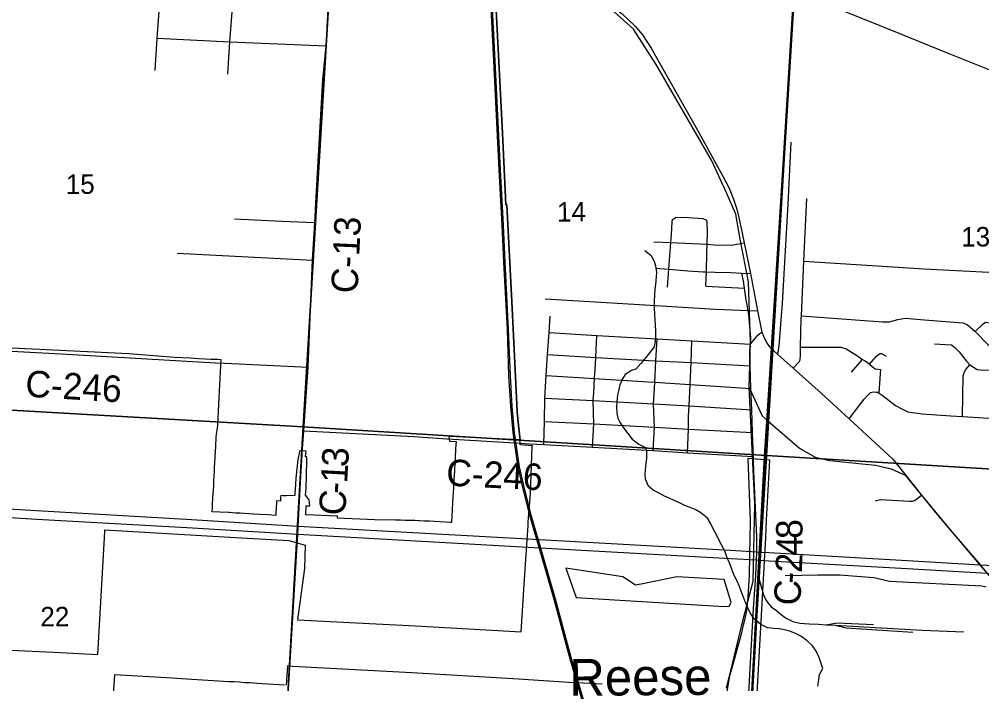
# Model space of a CAD drawing. Extents: x 114604 to 551442, y 316898 to 567001.
# Drawn here: x 211594 to 222509, y 352635 to 360166 of the extents above; entities that cross this region are included whole.
import ezdxf

# ---------------------------------------------------------------- set-up
doc = ezdxf.new("R2010")
doc.units = 0
for name, color, linetype in [('_CIVIL_CONSTRUCTION', 7, 'Continuous'), ('GE_P_Alignment_1000_Bearings', 7, 'Continuous'), ('GE_P_Alignment_1000_Cardinal_Points', 7, 'Continuous'), ('GE_P_Alignment_100_Cardinal_Points', 7, 'Continuous'), ('GE_P_Alignment_100_Stations', 7, 'Continuous'), ('GE_P_Alignment_500_Bearings', 7, 'Continuous'), ('GE_P_Alignment_500_Stations', 7, 'Continuous'), ('MT_X_Edge_Line', 7, 'Continuous'), ('PM_P_Cells', 7, 'Continuous'), ('PM_P_CL_Double_Solid', 7, 'Continuous'), ('PV_X_Curb', 7, 'Continuous'), ('SN_P_Signs', 7, 'Continuous')]:
    doc.layers.add(name, color=color, linetype=linetype)

msp = doc.modelspace()

# ---------------------------------------------------------------- linework, layer by layer
at = {"layer": 'GE_P_Alignment_1000_Bearings'}
msp.add_line((220743, 353304), (220845, 353298), dxfattribs=at)
for points in [[(218631, 350263), (217854, 352934), (217675, 353594), (217531, 354094), (217400, 354544), (217315, 354882), (217268, 355093), (217250, 355195), (217209, 355484), (217183, 355777), (217163, 356127), (217144, 356648), (217105, 357415), (217084, 357831), (217052, 358461), (216986, 359770), (216941, 360658), (216921, 360934), (216917, 360995), (216880, 361603), (216781, 362352), (216730, 362595), (216600, 362827)], [(216600, 362827), (216766, 362658), (216806, 362616), (216908, 362516), (216997, 362427), (217193, 362237), (217353, 362078), (217600, 361872), (217668, 361817), (217820, 361700), (217968, 361593), (218214, 361432), (218573, 361229), (218809, 361119), (219483, 360846), (219708, 360755), (220389, 360483), (221214, 360151), (221568, 360008), (222154, 359772), (222855, 359492)], [(219870, 355993), (219885, 356503), (219863, 357189), (219771, 357673), (219721, 357957), (219619, 358192), (219445, 358570), (218816, 359653), (218559, 360054), (218303, 360283), (218036, 360470), (217786, 360675), (217423, 361033), (217160, 361368), (217005, 361592), (216861, 361910), (216806, 362147), (216780, 362442), (216805, 362619)], [(218617, 350258), (217839, 352930), (217660, 353590), (217517, 354089), (217385, 354540), (217300, 354878), (217253, 355090), (217235, 355193), (217194, 355482), (217168, 355776), (217147, 356126), (217129, 356648), (217090, 357414), (217069, 357830), (217037, 358460), (216971, 359769), (216926, 360657), (216908, 360908), (216852, 361462)], [(219874, 352054), (219970, 353816), (220046, 355214), (220072, 355612), (220250, 358400), (220377, 360484)], [(219886, 352054), (219983, 353815), (220059, 355213), (220084, 355612), (220262, 358399), (220389, 360483)], [(219615, 352586), (219675, 352830), (219804, 353363), (219917, 353797), (219937, 354674), (219870, 355993)], [(219870, 355993), (220018, 355673), (220083, 355614)], [(220083, 355614), (220442, 355306), (220619, 355201), (220787, 355164), (221154, 355126), (221307, 355112), (221481, 355069), (221639, 354999), (222004, 354554), (222478, 353990), (222796, 353621), (223021, 353436), (223451, 353137), (223888, 352925), (224349, 352693), (224986, 352370)], [(219983, 353815), (220011, 353723), (220030, 353653), (220052, 353597), (220083, 353552), (220122, 353507), (220180, 353464), (220237, 353416), (220290, 353379), (220366, 353342), (220446, 353320), (220550, 353315), (220658, 353309), (220743, 353304)], [(220743, 353304), (220866, 353326), (221281, 353305)], [(220845, 353298), (220971, 353268), (221729, 353218)], [(220845, 353298), (221106, 353282), (221833, 353242), (222305, 353224)]]:
    msp.add_lwpolyline(points, dxfattribs=at)
at = {"layer": 'GE_P_Alignment_1000_Cardinal_Points'}
msp.add_line((213386, 357516), (214921, 357436), dxfattribs=at)
for points in [[(213137, 359584), (213159, 359950), (213235, 360975)], [(213958, 359543), (213982, 359911), (214061, 360928)], [(213159, 359950), (213982, 359911), (215075, 359866)], [(214037, 357903), (214571, 357878), (214946, 357861)]]:
    msp.add_lwpolyline(points, dxfattribs=at)
at = {"layer": 'GE_P_Alignment_100_Cardinal_Points'}
for p, q in [((219381, 357139), (219817, 357117)), ((221030, 356166), (221158, 356311))]:
    msp.add_line(p, q, dxfattribs=at)
for points in [[(220195, 356368), (220211, 356464), (220250, 356948), (220312, 358071), (220347, 358771)], [(220371, 356211), (220437, 356285), (220448, 356307), (220452, 356359), (220455, 356451), (220462, 356783), (220463, 356804), (220492, 357425), (220524, 358133)], [(218946, 357130), (218961, 357333), (218983, 357635), (218990, 357728), (218997, 357869), (219002, 357897), (219018, 357905)], [(219018, 357905), (219040, 357923), (219182, 357919), (219347, 357908), (219389, 357889)], [(219381, 357139), (219386, 357302), (219393, 357520), (219395, 357615), (219398, 357749), (219395, 357869), (219389, 357889)], [(218791, 357644), (218983, 357635), (219395, 357615), (219474, 357611), (219612, 357604), (219690, 357609), (219816, 357633)], [(218808, 357345), (218961, 357333), (219177, 357315), (219349, 357303), (219386, 357302), (219487, 357298), (219662, 357294), (219789, 357288), (219885, 357284)], [(220492, 357425), (221855, 357339), (222660, 357294), (223022, 357273)], [(219888, 356482), (219889, 356559), (219879, 356683), (219868, 356815), (219859, 356865), (219839, 356985), (219817, 357117), (219806, 357196), (219789, 357288)], [(217557, 356997), (218564, 356938), (219488, 356881), (219859, 356865), (219967, 356860)], [(217543, 355346), (217552, 355607), (217555, 355873), (217571, 356129), (217586, 356366), (217602, 356615), (217614, 356799)], [(220463, 356804), (221382, 356735), (221461, 356738), (221558, 356763), (221642, 356778), (221861, 356760), (222296, 356727), (222344, 356705), (222435, 356628), (222579, 356481), (222606, 356459), (222629, 356455), (222967, 356429)], [(222435, 356628), (222525, 356713), (222550, 356731), (222576, 356730), (222595, 356724), (222697, 356699)], [(217602, 356615), (218145, 356582), (218827, 356544), (219223, 356523), (219888, 356482)], [(218093, 355316), (218110, 355580), (218104, 355844), (218110, 355933), (218119, 356093), (218128, 356256), (218132, 356332), (218145, 356582)], [(219888, 356482), (219914, 356516), (219937, 356545), (219951, 356564), (219970, 356586), (219994, 356603), (220016, 356618)], [(218782, 355278), (218797, 355543), (218787, 355809), (218793, 355922), (218800, 356054), (218813, 356295), (218827, 356544)], [(219171, 355252), (219185, 355522), (219184, 355667), (219190, 355786), (219202, 356026), (219213, 356277), (219223, 356523)], [(219921, 355210), (219909, 355481), (219902, 355739), (219891, 355982), (219882, 356237), (219877, 356400), (219881, 356457), (219888, 356482)], [(221972, 356489), (222166, 356475), (222203, 356447), (222253, 356397), (222337, 356290), (222372, 356251), (222375, 356248), (222416, 356223), (222456, 356197), (222490, 356193), (222626, 356187)], [(217586, 356366), (218132, 356332), (218805, 356295), (218813, 356295), (219213, 356277), (219882, 356237)], [(220455, 356451), (220911, 356449), (220971, 356432), (221098, 356353), (221158, 356311), (221189, 356290), (221227, 356264), (221235, 356257), (221266, 356229), (221300, 356205), (221366, 356196)], [(221235, 356257), (221314, 356347), (221352, 356378), (221372, 356376), (221425, 356349)], [(222289, 355664), (222298, 356125), (222308, 356163), (222328, 356198), (222372, 356251)], [(221344, 355929), (221357, 356093), (221366, 356196)], [(217571, 356129), (218119, 356093), (218795, 356054), (218800, 356054), (219198, 356026), (219202, 356026), (219891, 355982)], [(221007, 355637), (221177, 355862), (221213, 355903), (221247, 355937), (221283, 355944), (221313, 355940), (221329, 355939), (221344, 355929)], [(221344, 355929), (221381, 355905), (221462, 355840), (221531, 355790), (221601, 355749), (221670, 355716), (221834, 355693), (222157, 355673), (222289, 355664), (222590, 355643), (222596, 355642), (222674, 355626), (222741, 355598), (222785, 355569), (222819, 355545), (222872, 355536), (222909, 355533), (223397, 355499)], [(217555, 355873), (218104, 355844), (218787, 355809), (219190, 355786), (219902, 355739)], [(217552, 355607), (218110, 355580), (218797, 355543), (219185, 355522), (219909, 355481)], [(221304, 354709), (221359, 354722), (221691, 354705), (221725, 354705), (221753, 354715), (221825, 354774)], [(220281, 353860), (220651, 353871), (220769, 353870), (220898, 353868), (221286, 353838), (221463, 353797), (222511, 353744), (222560, 353735)]]:
    msp.add_lwpolyline(points, dxfattribs=at)
at = {"layer": 'GE_P_Alignment_100_Stations'}
for points in [[(211491, 353017), (211986, 352991), (212486, 352965), (212565, 354355), (212566, 354381), (213982, 354298), (214650, 354258), (214838, 354207), (214828, 353940), (214803, 353749), (214751, 353359), (216087, 353293), (216490, 353270), (217285, 353225), (217318, 353759), (217338, 354042), (217364, 354429), (217366, 354468), (217390, 354795), (217412, 355319), (217413, 355333), (217274, 355342), (217275, 355376), (217275, 355399), (217254, 355560), (217242, 355718), (217232, 355879), (217179, 356967), (217125, 358062), (217112, 358063), (217073, 358876), (217044, 359466), (216980, 360710)], [(216980, 360710), (217044, 359466), (217073, 358876), (217112, 358063), (217125, 358062), (217179, 356967), (217232, 355879), (217242, 355718), (217254, 355560), (217275, 355399), (216466, 355438), (216472, 355384), (216548, 355382), (216543, 355298), (216537, 355197), (216535, 355148), (216529, 355049), (216526, 355000), (216523, 354950), (216520, 354900), (216517, 354850), (216514, 354800), (216511, 354749), (216508, 354699), (216502, 354594), (216499, 354540), (216495, 354461), (216482, 354462), (216425, 354465), (216298, 354473), (216245, 354476), (216189, 354479), (216134, 354482), (216122, 354483), (216080, 354484), (216025, 354485), (215971, 354486), (215916, 354487), (215861, 354487), (215624, 354491), (215203, 354510), (215204, 354536), (214845, 354551), (214848, 354652), (214889, 354651), (214881, 354720), (214841, 354773), (214846, 354849), (214848, 354900), (214852, 354955), (214854, 355208), (214842, 355208), (214847, 355270), (214775, 355278), (214756, 355197), (214750, 355147), (214745, 355098), (214740, 355048), (214733, 354982), (214732, 354974), (214727, 354892), (214721, 354790), (214720, 354768), (214623, 354766), (214585, 354766), (214560, 354767), (214558, 354746), (214556, 354706), (214512, 354709), (214511, 354684), (214504, 354576), (214502, 354542), (214416, 354548), (214327, 354553), (214250, 354558), (214199, 354561), (214149, 354564), (214099, 354567), (214047, 354570), (213980, 354574), (213966, 354575), (213868, 354580), (213783, 354585), (213786, 354635), (213787, 354669), (213791, 354743), (213796, 354826), (213799, 354889), (213802, 354939), (213805, 354989), (213808, 355039), (213810, 355088), (213813, 355138), (213816, 355199), (213820, 355271), (213823, 355321), (213829, 355435), (213845, 355560), (213857, 355804), (213879, 356240), (213880, 356256), (213883, 356305), (213840, 356308), (213770, 356311), (213700, 356315), (213630, 356319), (213533, 356325), (213447, 356329), (213356, 356334), (212837, 356373), (211511, 356438)], [(219963, 352523), (220037, 353888), (220059, 354289), (220069, 354488), (220106, 355169), (219995, 355176), (219856, 355189), (219881, 354486), (219882, 354435), (219878, 354307), (219873, 353866), (219857, 353620), (219842, 353460), (219821, 353372), (219800, 353284), (219779, 353196), (219674, 352813), (219649, 352725), (219632, 352636), (219617, 352545)], [(218205, 352630), (217991, 352641), (217884, 352646), (217254, 352687), (216494, 352731), (216046, 352757), (214694, 352829), (214635, 352837), (214622, 352619)], [(214602, 352620), (214293, 352639), (214256, 352641), (214212, 352644), (214152, 352647), (214092, 352651), (214032, 352655), (213994, 352657), (213972, 352658), (213912, 352662), (213852, 352665), (213792, 352669), (213732, 352673), (213673, 352676), (213613, 352680), (213553, 352683), (213493, 352687), (213433, 352691), (213329, 352697), (212675, 352737), (212660, 352509)]]:
    msp.add_lwpolyline(points, dxfattribs=at)
at = {"layer": 'GE_P_Alignment_500_Bearings'}
for p, q in [((214871, 356221), (214906, 357066)), ((213924, 356268), (214871, 356221)), ((214823, 355502), (214871, 356221)), ((214804, 355247), (214823, 355502)), ((219921, 355156), (219921, 355210)), ((214666, 352884), (214749, 354271)), ((214503, 350163), (214666, 352884))]:
    msp.add_line(p, q, dxfattribs=at)
for points in [[(217865, 360675), (218295, 360333), (218431, 360227), (218580, 360089), (218660, 359989), (218761, 359837), (219301, 358882), (219575, 358381), (219645, 358253), (219694, 358126), (219731, 358015), (219755, 357918), (219816, 357633), (219885, 357284), (219967, 356860), (220016, 356618)], [(215078, 359918), (215097, 360290), (215101, 360338)], [(214906, 357066), (214921, 357436), (214946, 357861), (214963, 358155), (215035, 359478), (215075, 359866), (215078, 359918)], [(220016, 356618), (220033, 356573), (220052, 356532), (220077, 356491), (220102, 356453), (220126, 356430), (220152, 356409), (220195, 356368), (220371, 356211), (220686, 355928), (221007, 355637), (221452, 355226), (221495, 355184), (221551, 355121), (221825, 354774), (222061, 354489)], [(211505, 356405), (212068, 356375), (213819, 356273), (213924, 356268)], [(214823, 355502), (216069, 355436), (216443, 355411)], [(216443, 355411), (216516, 355406), (217275, 355361), (217385, 355354)], [(217385, 355354), (217543, 355346), (218093, 355316), (218782, 355278), (219171, 355252), (219921, 355210)], [(214789, 354989), (214802, 355231), (214804, 355247)], [(219923, 353539), (219946, 353861), (219954, 354034), (219958, 354127), (219959, 354295), (219948, 354551), (219928, 354956), (219921, 355150), (219921, 355156)], [(214749, 354271), (214752, 354327), (214757, 354418), (214789, 354989)], [(222061, 354489), (222172, 354354), (222495, 353979), (222571, 353886), (222715, 353711), (222800, 353621), (222887, 353536), (223193, 353317), (223404, 353165)], [(219766, 350915), (219770, 350962), (219809, 351479), (219860, 352391), (219920, 353492), (219923, 353539)]]:
    msp.add_lwpolyline(points, dxfattribs=at)
at = {"layer": 'GE_P_Alignment_500_Stations'}
for points in [[(220016, 354124), (220010, 354124), (219958, 354127), (219660, 354145), (217561, 354262), (214757, 354418), (213488, 354497), (211789, 354593), (210620, 354661), (209344, 354732), (208878, 354760), (208039, 354807)], [(221664, 353937), (220099, 354024), (219954, 354034), (219665, 354051), (217565, 354168), (214752, 354327), (213493, 354402), (211793, 354498), (210624, 354567), (209339, 354639), (208883, 354666), (208122, 354708)], [(221598, 354031), (220094, 354119), (220016, 354124)], [(224755, 354124), (224560, 354076), (224303, 354030), (224070, 353992), (223872, 353968), (223639, 353953), (223436, 353944), (223341, 353945), (223146, 353947), (222851, 353961), (222495, 353979), (221598, 354031)], [(223876, 353874), (223644, 353859), (223441, 353849), (223150, 353852), (222855, 353866), (222571, 353886), (221664, 353937)]]:
    msp.add_lwpolyline(points, dxfattribs=at)
at = {"layer": 'MT_X_Edge_Line'}
for points in [[(217792, 353945), (217909, 353614)], [(217909, 353614), (219589, 353509), (219643, 353516), (219669, 353554), (219589, 353815), (219052, 353847), (218648, 353765), (218584, 353754), (218438, 353845), (217792, 353945)]]:
    msp.add_lwpolyline(points, dxfattribs=at)
at = {"layer": 'PM_P_Cells'}
for points in [[(218689, 357546), (218755, 357491), (218793, 357423), (218811, 357371), (218821, 357297), (218818, 357245), (218808, 357161), (218800, 357105), (218796, 357047), (218794, 356962), (218794, 356892), (218797, 356824), (218801, 356762), (218807, 356696), (218811, 356638), (218811, 356582), (218807, 356516), (218795, 356453), (218742, 356385), (218698, 356331), (218644, 356263), (218588, 356199), (218538, 356185), (218466, 356141), (218434, 356089), (218406, 356023), (218392, 355971), (218379, 355911), (218369, 355831), (218365, 355771), (218369, 355703), (218383, 355646), (218409, 355592), (218445, 355536), (218494, 355472), (218546, 355408), (218622, 355350), (218694, 355314), (218712, 355251)], [(218693, 355005), (218696, 355061), (218703, 355135), (218709, 355187), (218712, 355251)], [(220651, 352606), (220663, 352682), (220668, 352740), (220706, 352808), (220681, 352886), (220662, 352941), (220632, 353005), (220589, 353065), (220526, 353124), (220458, 353175), (220397, 353203), (220333, 353232), (220273, 353247), (220211, 353257), (220155, 353262), (220081, 353269), (220004, 353305), (219928, 353370), (219883, 353437), (219856, 353497), (219823, 353576), (219801, 353634), (219782, 353684), (219760, 353738), (219737, 353797), (219703, 353861), (219676, 353934), (219649, 354004), (219623, 354062), (219604, 354120), (219575, 354175), (219537, 354245), (219500, 354324), (219463, 354390), (219437, 354447), (219398, 354511), (219325, 354572), (219259, 354611), (219201, 354631), (219149, 354650), (219096, 354678), (219038, 354705), (218970, 354733), (218913, 354762), (218849, 354793), (218783, 354829), (218728, 354876), (218697, 354954), (218693, 355005)]]:
    msp.add_lwpolyline(points, dxfattribs=at)
at = {"layer": 'SN_P_Signs'}
for points in [[(215135, 360875), (214813, 355546), (209446, 355851), (209780, 361186)], [(220384, 360558), (220066, 355223), (214813, 355546), (215135, 360875)], [(225716, 360242), (225412, 355208), (225387, 354900), (220066, 355223), (220384, 360558)], [(209446, 355851), (214813, 355546), (214507, 350209), (209148, 350532)], [(214813, 355546), (220066, 355223), (219745, 349915), (214507, 350209)], [(225387, 354900), (225068, 349650), (225060, 349570), (219745, 349915), (220066, 355223)]]:
    msp.add_lwpolyline(points, close=True, dxfattribs=at)

# ---------------------------------------------------------------- texts
at = {"layer": '_CIVIL_CONSTRUCTION'}
msp.add_text('Reese', height=417, rotation=0.4137, dxfattribs=at).set_placement((217833, 352498))
at = {"layer": 'PM_P_CL_Double_Solid'}
for s, rotation, p in [('C-13', 87.347, (215430, 357055)), ('C-246', 356.5444, (211657, 355889)), ('3', 86.6177, (215322, 355086)), ('C-246', 357.1434, (216431, 354881)), ('1', 86.7973, (215312, 354903)), ('-', 86.8177, (215305, 354782)), ('C', 86.823, (215291, 354537)), ('8', 91.455, (220479, 354280)), ('4', 89.0762, (220476, 354082)), ('2', 87.5078, (220468, 353888)), ('-', 87.215, (220462, 353763)), ('C', 87.1374, (220450, 353517))]:
    msp.add_text(s, height=300, rotation=rotation, dxfattribs=at).set_placement(p)
at = {"layer": 'PV_X_Curb'}
for s, rotation, p in [('15', 0.4136, (212122, 358185)), ('14', 0.4137, (217693, 357872)), ('13', 0.4138, (222276, 357589)), ('22', 0.4136, (211834, 353284))]:
    msp.add_text(s, height=221, rotation=rotation, dxfattribs=at).set_placement(p)

doc.saveas('drawing.dxf')
